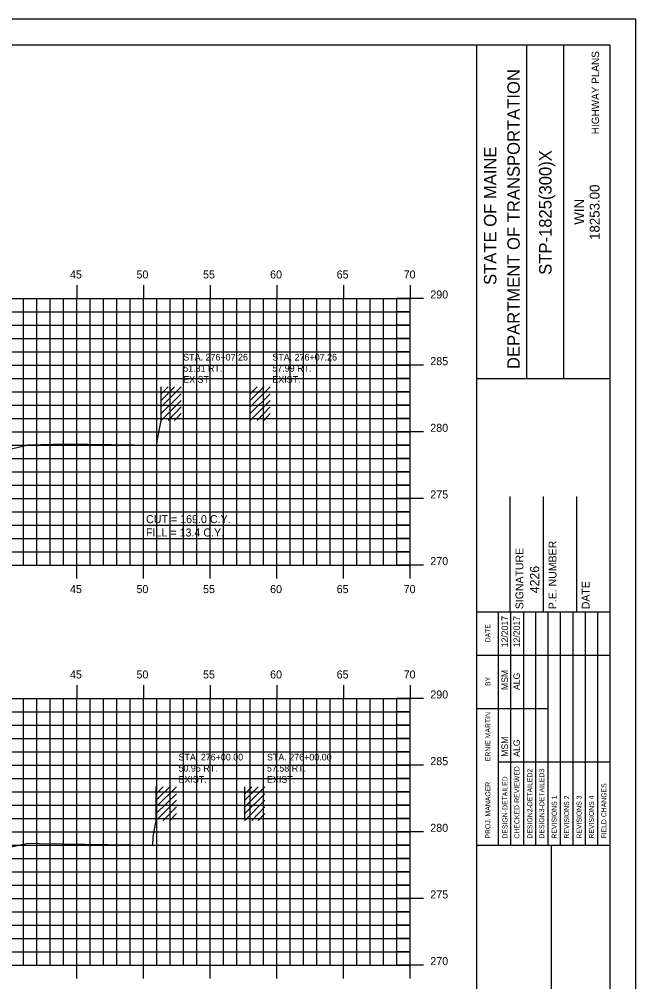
# Model space of a CAD drawing. Extents: x 853785 to 853955, y 366268 to 366378.
# Drawn here: x 853909.1 to 853955.3, y 366306 to 366378.2 of the extents above; entities that cross this region are included whole.
import ezdxf

# ---------------------------------------------------------------- set-up
doc = ezdxf.new("R2010")
doc.units = 0
for name, color, linetype in [('ANNOTATION', 7, 'Continuous'), ('BORDER', 7, 'Continuous'), ('D_Text_Monospaced', 7, 'Continuous'), ('H_V ANNOTATION', 7, 'Continuous'), ('HIGHWAY_TITLE', 7, 'Continuous'), ('MAJOR', 7, 'Continuous'), ('MINOR', 7, 'Continuous'), ('PLOT BOUNDARY', 7, 'Continuous'), ('S_Buildings', 7, 'Continuous'), ('S_Roadway_Centerline', 7, 'Continuous')]:
    doc.layers.add(name, color=color, linetype=linetype)

msp = doc.modelspace()

# ---------------------------------------------------------------- linework, layer by layer
at = {"layer": 'BORDER'}
for p, q in [((853953.435, 366376.236), (853793.435, 366376.236)), ((853943.435, 366271.236), (853943.435, 366376.239)), ((853947.164, 366351.234), (853947.164, 366376.234)), ((853949.959, 366351.234), (853949.959, 366376.234)), ((853953.435, 366271.236), (853953.435, 366376.236)), ((853943.436, 366351.231), (853953.435, 366351.231)), ((853945.935, 366333.739), (853945.935, 366342.387)), ((853948.435, 366333.739), (853948.435, 366342.387)), ((853950.935, 366333.739), (853950.935, 366342.387)), ((853943.435, 366333.739), (853953.435, 366333.739)), ((853943.435, 366316.239), (853953.435, 366316.239)), ((853949.027, 366281.239), (853949.027, 366316.239))]:
    msp.add_line(p, q, dxfattribs=at)
for points in [[(853945.05, 366330.489), (853945.05, 366333.739)], [(853945.983, 366316.242), (853945.983, 366333.739)], [(853946.915, 366333.739), (853946.915, 366316.242)], [(853947.846, 366316.242), (853947.846, 366333.739)], [(853948.778, 366316.242), (853948.778, 366333.739)], [(853949.71, 366316.242), (853949.71, 366333.739)], [(853950.641, 366316.242), (853950.641, 366333.739)], [(853951.573, 366316.242), (853951.573, 366333.739)], [(853952.505, 366316.242), (853952.505, 366333.739)], [(853945.051, 366316.242), (853945.051, 366333.033)], [(853943.435, 366330.489), (853953.435, 366330.489)], [(853943.435, 366326.489), (853945.051, 366326.489)], [(853945.05, 366326.489), (853948.777, 366326.489)], [(853945.05, 366322.489), (853953.435, 366322.489)]]:
    msp.add_lwpolyline(points, dxfattribs=at)
at = {"layer": 'MAJOR'}
for p, q in [((853913.435, 366358.238), (853913.435, 366357.236)), ((853918.435, 366358.238), (853918.435, 366357.236)), ((853923.435, 366358.238), (853923.435, 366357.236)), ((853928.435, 366358.238), (853928.435, 366357.236)), ((853933.435, 366358.238), (853933.435, 366357.236)), ((853938.435, 366358.238), (853938.435, 366357.236)), ((853798.435, 366357.236), (853938.435, 366357.236)), ((853798.435, 366357.236), (853938.435, 366357.236)), ((853913.435, 366337.236), (853913.435, 366357.236)), ((853918.435, 366337.236), (853918.435, 366357.236)), ((853923.435, 366337.236), (853923.435, 366357.236)), ((853928.435, 366337.236), (853928.435, 366357.236)), ((853933.435, 366337.236), (853933.435, 366357.236)), ((853939.437, 366357.236), (853937.433, 366357.236)), ((853938.435, 366337.236), (853938.435, 366357.236)), ((853938.435, 366337.236), (853938.435, 366357.236)), ((853798.435, 366352.236), (853938.435, 366352.236)), ((853939.437, 366352.236), (853937.433, 366352.236)), ((853798.435, 366347.236), (853938.435, 366347.236)), ((853939.437, 366347.236), (853937.433, 366347.236)), ((853798.435, 366342.236), (853938.435, 366342.236)), ((853939.437, 366342.236), (853937.433, 366342.236)), ((853798.435, 366337.236), (853938.435, 366337.236)), ((853798.435, 366337.236), (853938.435, 366337.236)), ((853913.435, 366336.234), (853913.435, 366337.236)), ((853918.435, 366336.234), (853918.435, 366337.236)), ((853923.435, 366336.234), (853923.435, 366337.236)), ((853928.435, 366336.234), (853928.435, 366337.236)), ((853933.435, 366336.234), (853933.435, 366337.236)), ((853939.437, 366337.236), (853937.433, 366337.236)), ((853938.435, 366336.234), (853938.435, 366337.236)), ((853913.435, 366328.238), (853913.435, 366327.236)), ((853918.435, 366328.238), (853918.435, 366327.236)), ((853923.435, 366328.238), (853923.435, 366327.236)), ((853928.435, 366328.238), (853928.435, 366327.236)), ((853933.435, 366328.238), (853933.435, 366327.236)), ((853938.435, 366328.238), (853938.435, 366327.236)), ((853798.435, 366327.236), (853938.435, 366327.236)), ((853798.435, 366327.236), (853938.435, 366327.236)), ((853913.435, 366307.236), (853913.435, 366327.236)), ((853918.435, 366307.236), (853918.435, 366327.236)), ((853923.435, 366307.236), (853923.435, 366327.236)), ((853928.435, 366307.236), (853928.435, 366327.236)), ((853933.435, 366307.236), (853933.435, 366327.236)), ((853939.437, 366327.236), (853937.433, 366327.236)), ((853938.435, 366307.236), (853938.435, 366327.236)), ((853938.435, 366307.236), (853938.435, 366327.236)), ((853798.435, 366322.236), (853938.435, 366322.236)), ((853939.437, 366322.236), (853937.433, 366322.236)), ((853798.435, 366317.236), (853938.435, 366317.236)), ((853939.437, 366317.236), (853937.433, 366317.236)), ((853798.435, 366312.236), (853938.435, 366312.236)), ((853939.437, 366312.236), (853937.433, 366312.236)), ((853798.435, 366307.236), (853938.435, 366307.236)), ((853798.435, 366307.236), (853938.435, 366307.236)), ((853913.435, 366306.234), (853913.435, 366307.236)), ((853918.435, 366306.234), (853918.435, 366307.236)), ((853923.435, 366306.234), (853923.435, 366307.236)), ((853928.435, 366306.234), (853928.435, 366307.236)), ((853933.435, 366306.234), (853933.435, 366307.236)), ((853939.437, 366307.236), (853937.433, 366307.236)), ((853938.435, 366306.234), (853938.435, 366307.236))]:
    msp.add_line(p, q, dxfattribs=at)
at = {"layer": 'MINOR'}
for p, q in [((853909.435, 366337.236), (853909.435, 366357.236)), ((853910.435, 366337.236), (853910.435, 366357.236)), ((853911.435, 366337.236), (853911.435, 366357.236)), ((853912.435, 366337.236), (853912.435, 366357.236)), ((853914.435, 366337.236), (853914.435, 366357.236)), ((853915.435, 366337.236), (853915.435, 366357.236)), ((853916.435, 366337.236), (853916.435, 366357.236)), ((853917.435, 366337.236), (853917.435, 366357.236)), ((853919.435, 366337.236), (853919.435, 366357.236)), ((853920.435, 366337.236), (853920.435, 366357.236)), ((853921.435, 366337.236), (853921.435, 366357.236)), ((853922.435, 366337.236), (853922.435, 366357.236)), ((853924.435, 366337.236), (853924.435, 366357.236)), ((853925.435, 366337.236), (853925.435, 366357.236)), ((853926.435, 366337.236), (853926.435, 366357.236)), ((853927.435, 366337.236), (853927.435, 366357.236)), ((853929.435, 366337.236), (853929.435, 366357.236)), ((853930.435, 366337.236), (853930.435, 366357.236)), ((853931.435, 366337.236), (853931.435, 366357.236)), ((853932.435, 366337.236), (853932.435, 366357.236)), ((853934.435, 366337.236), (853934.435, 366357.236)), ((853935.435, 366337.236), (853935.435, 366357.236)), ((853936.435, 366337.236), (853936.435, 366357.236)), ((853937.435, 366337.236), (853937.435, 366357.236)), ((853798.435, 366356.236), (853938.435, 366356.236)), ((853938.435, 366356.236), (853937.433, 366356.236)), ((853798.435, 366355.236), (853938.435, 366355.236)), ((853938.435, 366355.236), (853937.433, 366355.236)), ((853798.435, 366354.236), (853938.435, 366354.236)), ((853938.435, 366354.236), (853937.433, 366354.236)), ((853798.435, 366353.236), (853938.435, 366353.236)), ((853938.435, 366353.236), (853937.433, 366353.236)), ((853798.435, 366351.236), (853938.435, 366351.236)), ((853938.435, 366351.236), (853937.433, 366351.236)), ((853798.435, 366350.236), (853938.435, 366350.236)), ((853938.435, 366350.236), (853937.433, 366350.236)), ((853798.435, 366349.236), (853938.435, 366349.236)), ((853938.435, 366349.236), (853937.433, 366349.236)), ((853798.435, 366348.236), (853938.435, 366348.236)), ((853938.435, 366348.236), (853937.433, 366348.236)), ((853798.435, 366346.236), (853938.435, 366346.236)), ((853938.435, 366346.236), (853937.433, 366346.236)), ((853798.435, 366345.236), (853938.435, 366345.236)), ((853938.435, 366345.236), (853937.433, 366345.236)), ((853798.435, 366344.236), (853938.435, 366344.236)), ((853938.435, 366344.236), (853937.433, 366344.236)), ((853798.435, 366343.236), (853938.435, 366343.236)), ((853938.435, 366343.236), (853937.433, 366343.236)), ((853798.435, 366341.236), (853938.435, 366341.236)), ((853938.435, 366341.236), (853937.433, 366341.236)), ((853798.435, 366340.236), (853938.435, 366340.236)), ((853938.435, 366340.236), (853937.433, 366340.236)), ((853798.435, 366339.236), (853938.435, 366339.236)), ((853938.435, 366339.236), (853937.433, 366339.236)), ((853798.435, 366338.236), (853938.435, 366338.236)), ((853938.435, 366338.236), (853937.433, 366338.236)), ((853909.435, 366307.236), (853909.435, 366327.236)), ((853910.435, 366307.236), (853910.435, 366327.236)), ((853911.435, 366307.236), (853911.435, 366327.236)), ((853912.435, 366307.236), (853912.435, 366327.236)), ((853914.435, 366307.236), (853914.435, 366327.236)), ((853915.435, 366307.236), (853915.435, 366327.236)), ((853916.435, 366307.236), (853916.435, 366327.236)), ((853917.435, 366307.236), (853917.435, 366327.236)), ((853919.435, 366307.236), (853919.435, 366327.236)), ((853920.435, 366307.236), (853920.435, 366327.236)), ((853921.435, 366307.236), (853921.435, 366327.236)), ((853922.435, 366307.236), (853922.435, 366327.236)), ((853924.435, 366307.236), (853924.435, 366327.236)), ((853925.435, 366307.236), (853925.435, 366327.236)), ((853926.435, 366307.236), (853926.435, 366327.236)), ((853927.435, 366307.236), (853927.435, 366327.236)), ((853929.435, 366307.236), (853929.435, 366327.236)), ((853930.435, 366307.236), (853930.435, 366327.236)), ((853931.435, 366307.236), (853931.435, 366327.236)), ((853932.435, 366307.236), (853932.435, 366327.236)), ((853934.435, 366307.236), (853934.435, 366327.236)), ((853935.435, 366307.236), (853935.435, 366327.236)), ((853936.435, 366307.236), (853936.435, 366327.236)), ((853937.435, 366307.236), (853937.435, 366327.236)), ((853798.435, 366326.236), (853938.435, 366326.236)), ((853938.435, 366326.236), (853937.433, 366326.236)), ((853798.435, 366325.236), (853938.435, 366325.236)), ((853938.435, 366325.236), (853937.433, 366325.236)), ((853798.435, 366324.236), (853938.435, 366324.236)), ((853938.435, 366324.236), (853937.433, 366324.236)), ((853798.435, 366323.236), (853938.435, 366323.236)), ((853938.435, 366323.236), (853937.433, 366323.236)), ((853798.435, 366321.236), (853938.435, 366321.236)), ((853938.435, 366321.236), (853937.433, 366321.236)), ((853798.435, 366320.236), (853938.435, 366320.236)), ((853938.435, 366320.236), (853937.433, 366320.236)), ((853798.435, 366319.236), (853938.435, 366319.236)), ((853938.435, 366319.236), (853937.433, 366319.236)), ((853798.435, 366318.236), (853938.435, 366318.236)), ((853938.435, 366318.236), (853937.433, 366318.236)), ((853798.435, 366316.236), (853938.435, 366316.236)), ((853938.435, 366316.236), (853937.433, 366316.236)), ((853798.435, 366315.236), (853938.435, 366315.236)), ((853938.435, 366315.236), (853937.433, 366315.236)), ((853798.435, 366314.236), (853938.435, 366314.236)), ((853938.435, 366314.236), (853937.433, 366314.236)), ((853798.435, 366313.236), (853938.435, 366313.236)), ((853938.435, 366313.236), (853937.433, 366313.236)), ((853798.435, 366311.236), (853938.435, 366311.236)), ((853938.435, 366311.236), (853937.433, 366311.236)), ((853798.435, 366310.236), (853938.435, 366310.236)), ((853938.435, 366310.236), (853937.433, 366310.236)), ((853798.435, 366309.236), (853938.435, 366309.236)), ((853938.435, 366309.236), (853937.433, 366309.236)), ((853798.435, 366308.236), (853938.435, 366308.236)), ((853938.435, 366308.236), (853937.433, 366308.236))]:
    msp.add_line(p, q, dxfattribs=at)
at = {"layer": 'PLOT BOUNDARY'}
msp.add_lwpolyline([(853785.342, 366268.177), (853955.342, 366268.177), (853955.342, 366378.177), (853785.342, 366378.177)], close=True, dxfattribs=at)
at = {"layer": 'S_Buildings'}
for p, q in [((853919.741, 366348.084), (853919.741, 366350.611)), ((853919.741, 366349.102), (853921.25, 366350.611)), ((853919.741, 366349.594), (853920.758, 366350.611)), ((853919.741, 366350.086), (853920.266, 366350.611)), ((853926.422, 366348.084), (853926.422, 366350.611)), ((853926.422, 366349.101), (853927.931, 366350.611)), ((853926.422, 366349.594), (853927.439, 366350.611)), ((853926.422, 366350.086), (853926.947, 366350.611)), ((853919.741, 366348.609), (853921.25, 366350.086)), ((853919.741, 366348.084), (853921.25, 366349.594)), ((853926.422, 366348.609), (853927.931, 366350.086)), ((853926.422, 366348.084), (853927.931, 366349.594)), ((853920.266, 366348.084), (853921.25, 366349.102)), ((853926.947, 366348.084), (853927.931, 366349.101)), ((853920.758, 366348.084), (853921.25, 366348.609)), ((853927.439, 366348.084), (853927.931, 366348.609)), ((853919.384, 366318.088), (853919.384, 366320.614)), ((853919.384, 366319.105), (853920.893, 366320.614)), ((853919.384, 366319.597), (853920.401, 366320.614)), ((853919.384, 366320.09), (853919.909, 366320.614)), ((853919.384, 366318.613), (853920.893, 366320.09)), ((853926.018, 366318.088), (853926.018, 366320.614)), ((853926.018, 366319.105), (853927.527, 366320.614)), ((853926.018, 366319.597), (853927.035, 366320.614)), ((853926.018, 366320.089), (853926.543, 366320.614)), ((853926.018, 366318.613), (853927.527, 366320.089)), ((853919.384, 366318.088), (853920.893, 366319.597)), ((853926.018, 366318.088), (853927.527, 366319.597)), ((853919.909, 366318.088), (853920.893, 366319.105)), ((853920.401, 366318.088), (853920.893, 366318.613)), ((853926.543, 366318.088), (853927.527, 366319.105)), ((853927.035, 366318.088), (853927.527, 366318.613))]:
    msp.add_line(p, q, dxfattribs=at)
at = {"layer": 'S_Roadway_Centerline'}
for points in [[(853904.739, 366345.062), (853909.779, 366346.258), (853912.598, 366346.326), (853919.436, 366346.229), (853919.452, 366346.565), (853919.741, 366348.085)], [(853838.725, 366314.689), (853855.908, 366315.417), (853857.83, 366315.517), (853868.288, 366315.249), (853868.644, 366315.24), (853868.847, 366315.234), (853882.135, 366314.869), (853884.311, 366314.754), (853885.655, 366314.706), (853893.071, 366314.358), (853893.518, 366314.336), (853894.57, 366314.291), (853894.6, 366314.31), (853895.035, 366314.674), (853895.651, 366314.661), (853899.147, 366314.784), (853902.857, 366314.887), (853903.385, 366314.96), (853909.745, 366316.389), (853910.623, 366316.347), (853919.12, 366316.227), (853919.151, 366316.863), (853919.384, 366318.089)]]:
    msp.add_lwpolyline(points, dxfattribs=at)

# ---------------------------------------------------------------- texts
at = {"layer": 'ANNOTATION'}
for s, p in [('CUT = 169.0 C.Y.', (853918.611, 366340.386)), ('FILL = 13.4 C.Y.', (853918.611, 366339.384))]:
    msp.add_text(s, height=0.6, dxfattribs=at).set_placement(p)
msp.add_text('4226', height=0.69, rotation=90, dxfattribs=at).set_placement((853948.1, 366335.13))
at = {"layer": 'BORDER'}
for s, height, p in [('DEPARTMENT OF TRANSPORTATION', 0.93176, (853946.642, 366351.942)), ('STATE OF MAINE', 0.93176, (853944.891, 366358.248)), ('STP-1825(300)X', 0.93176, (853949.027, 366359.008)), ('18253.00', 0.7453, (853952.631, 366361.623)), ('WIN', 0.7453, (853951.472, 366362.766)), ('P.E. NUMBER', 0.59055, (853949.396, 366333.932)), ('SIGNATURE', 0.5906, (853946.916, 366333.932)), ('DATE', 0.5906, (853951.877, 366333.932)), ('12/2017', 0.4845, (853945.758, 366331.081)), ('12/2017', 0.4845, (853946.653, 366331.081)), ('DATE', 0.3714, (853944.44, 366331.445)), ('MSM', 0.4845, (853945.758, 366327.872)), ('BY', 0.3714, (853944.44, 366328.174)), ('ALG', 0.4845, (853946.653, 366327.872)), ('ERNIE MARTIN', 0.37275, (853944.44, 366322.531)), ('MSM', 0.4845, (853945.758, 366322.863)), ('ALG', 0.4845, (853946.653, 366322.863)), ('CHECKED-REVIEWED', 0.37275, (853946.616, 366316.727)), ('DESIGN2-DETAILED2', 0.37275, (853947.585, 366316.727)), ('DESIGN3-DETAILED3', 0.37275, (853948.48, 366316.727)), ('PROJ. MANAGER', 0.37275, (853944.44, 366316.727)), ('DESIGN-DETAILED', 0.37275, (853945.722, 366316.727)), ('FIELD CHANGES', 0.37275, (853953.138, 366316.727)), ('REVISIONS 1', 0.37275, (853949.412, 366316.727)), ('REVISIONS 2', 0.37275, (853950.343, 366316.727)), ('REVISIONS 3', 0.37275, (853951.275, 366316.727)), ('REVISIONS 4', 0.37275, (853952.207, 366316.727))]:
    msp.add_text(s, height=height, rotation=90, dxfattribs=at).set_placement(p)
at = {"layer": 'D_Text_Monospaced'}
for s, height, p in [('STA. 276+07.26', 0.49998, (853921.407, 366352.583)), ('STA. 276+07.26', 0.49998, (853928.089, 366352.583)), ('51.31 RT.', 0.5, (853921.407, 366351.749)), ('57.99 RT.', 0.5, (853928.089, 366351.749)), ('EXIST. ', 0.5, (853921.407, 366350.909)), ('EXIST. ', 0.5, (853928.089, 366350.909)), ('STA. 276+00.00', 0.49998, (853921.051, 366322.587)), ('STA. 276+00.00', 0.49998, (853927.685, 366322.586)), ('50.95 RT.', 0.5, (853921.051, 366321.753)), ('57.58 RT.', 0.5, (853927.685, 366321.752)), ('EXIST. ', 0.5, (853921.051, 366320.913)), ('EXIST. ', 0.5, (853927.685, 366320.912))]:
    msp.add_text(s, height=height, dxfattribs=at).set_placement(p)
at = {"layer": 'H_V ANNOTATION'}
for s, p in [('45', (853912.913, 366358.736)), ('50', (853917.9, 366358.736)), ('55', (853922.892, 366358.736)), ('60', (853927.921, 366358.736)), ('65', (853932.913, 366358.736)), ('70', (853937.937, 366358.736)), ('290', (853939.935, 366357.236)), ('285', (853939.935, 366352.236)), ('280', (853939.935, 366347.236)), ('275', (853939.935, 366342.236)), ('270', (853939.935, 366337.236)), ('45', (853912.913, 366335.136)), ('50', (853917.9, 366335.136)), ('55', (853922.892, 366335.136)), ('60', (853927.921, 366335.136)), ('65', (853932.913, 366335.136)), ('70', (853937.937, 366335.136)), ('45', (853912.913, 366328.736)), ('50', (853917.9, 366328.736)), ('55', (853922.892, 366328.736)), ('60', (853927.921, 366328.736)), ('65', (853932.913, 366328.736)), ('70', (853937.937, 366328.736)), ('290', (853939.935, 366327.236)), ('285', (853939.935, 366322.236)), ('280', (853939.935, 366317.236)), ('275', (853939.935, 366312.236)), ('270', (853939.935, 366307.236))]:
    msp.add_text(s, height=0.6, dxfattribs=at).set_placement(p)
at = {"layer": 'HIGHWAY_TITLE'}
msp.add_text('HIGHWAY PLANS', height=0.55901, rotation=90, dxfattribs=at).set_placement((853952.594, 366369.552))

doc.saveas('drawing.dxf')
